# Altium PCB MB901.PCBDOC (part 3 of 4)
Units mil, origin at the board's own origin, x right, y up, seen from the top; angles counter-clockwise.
Board outline 4505 x 7005 mil, 4 copper layers (TopLayer, GND, VCC, BottomLayer); 333 components, 312 nets, 1570 pads, 794 vias.
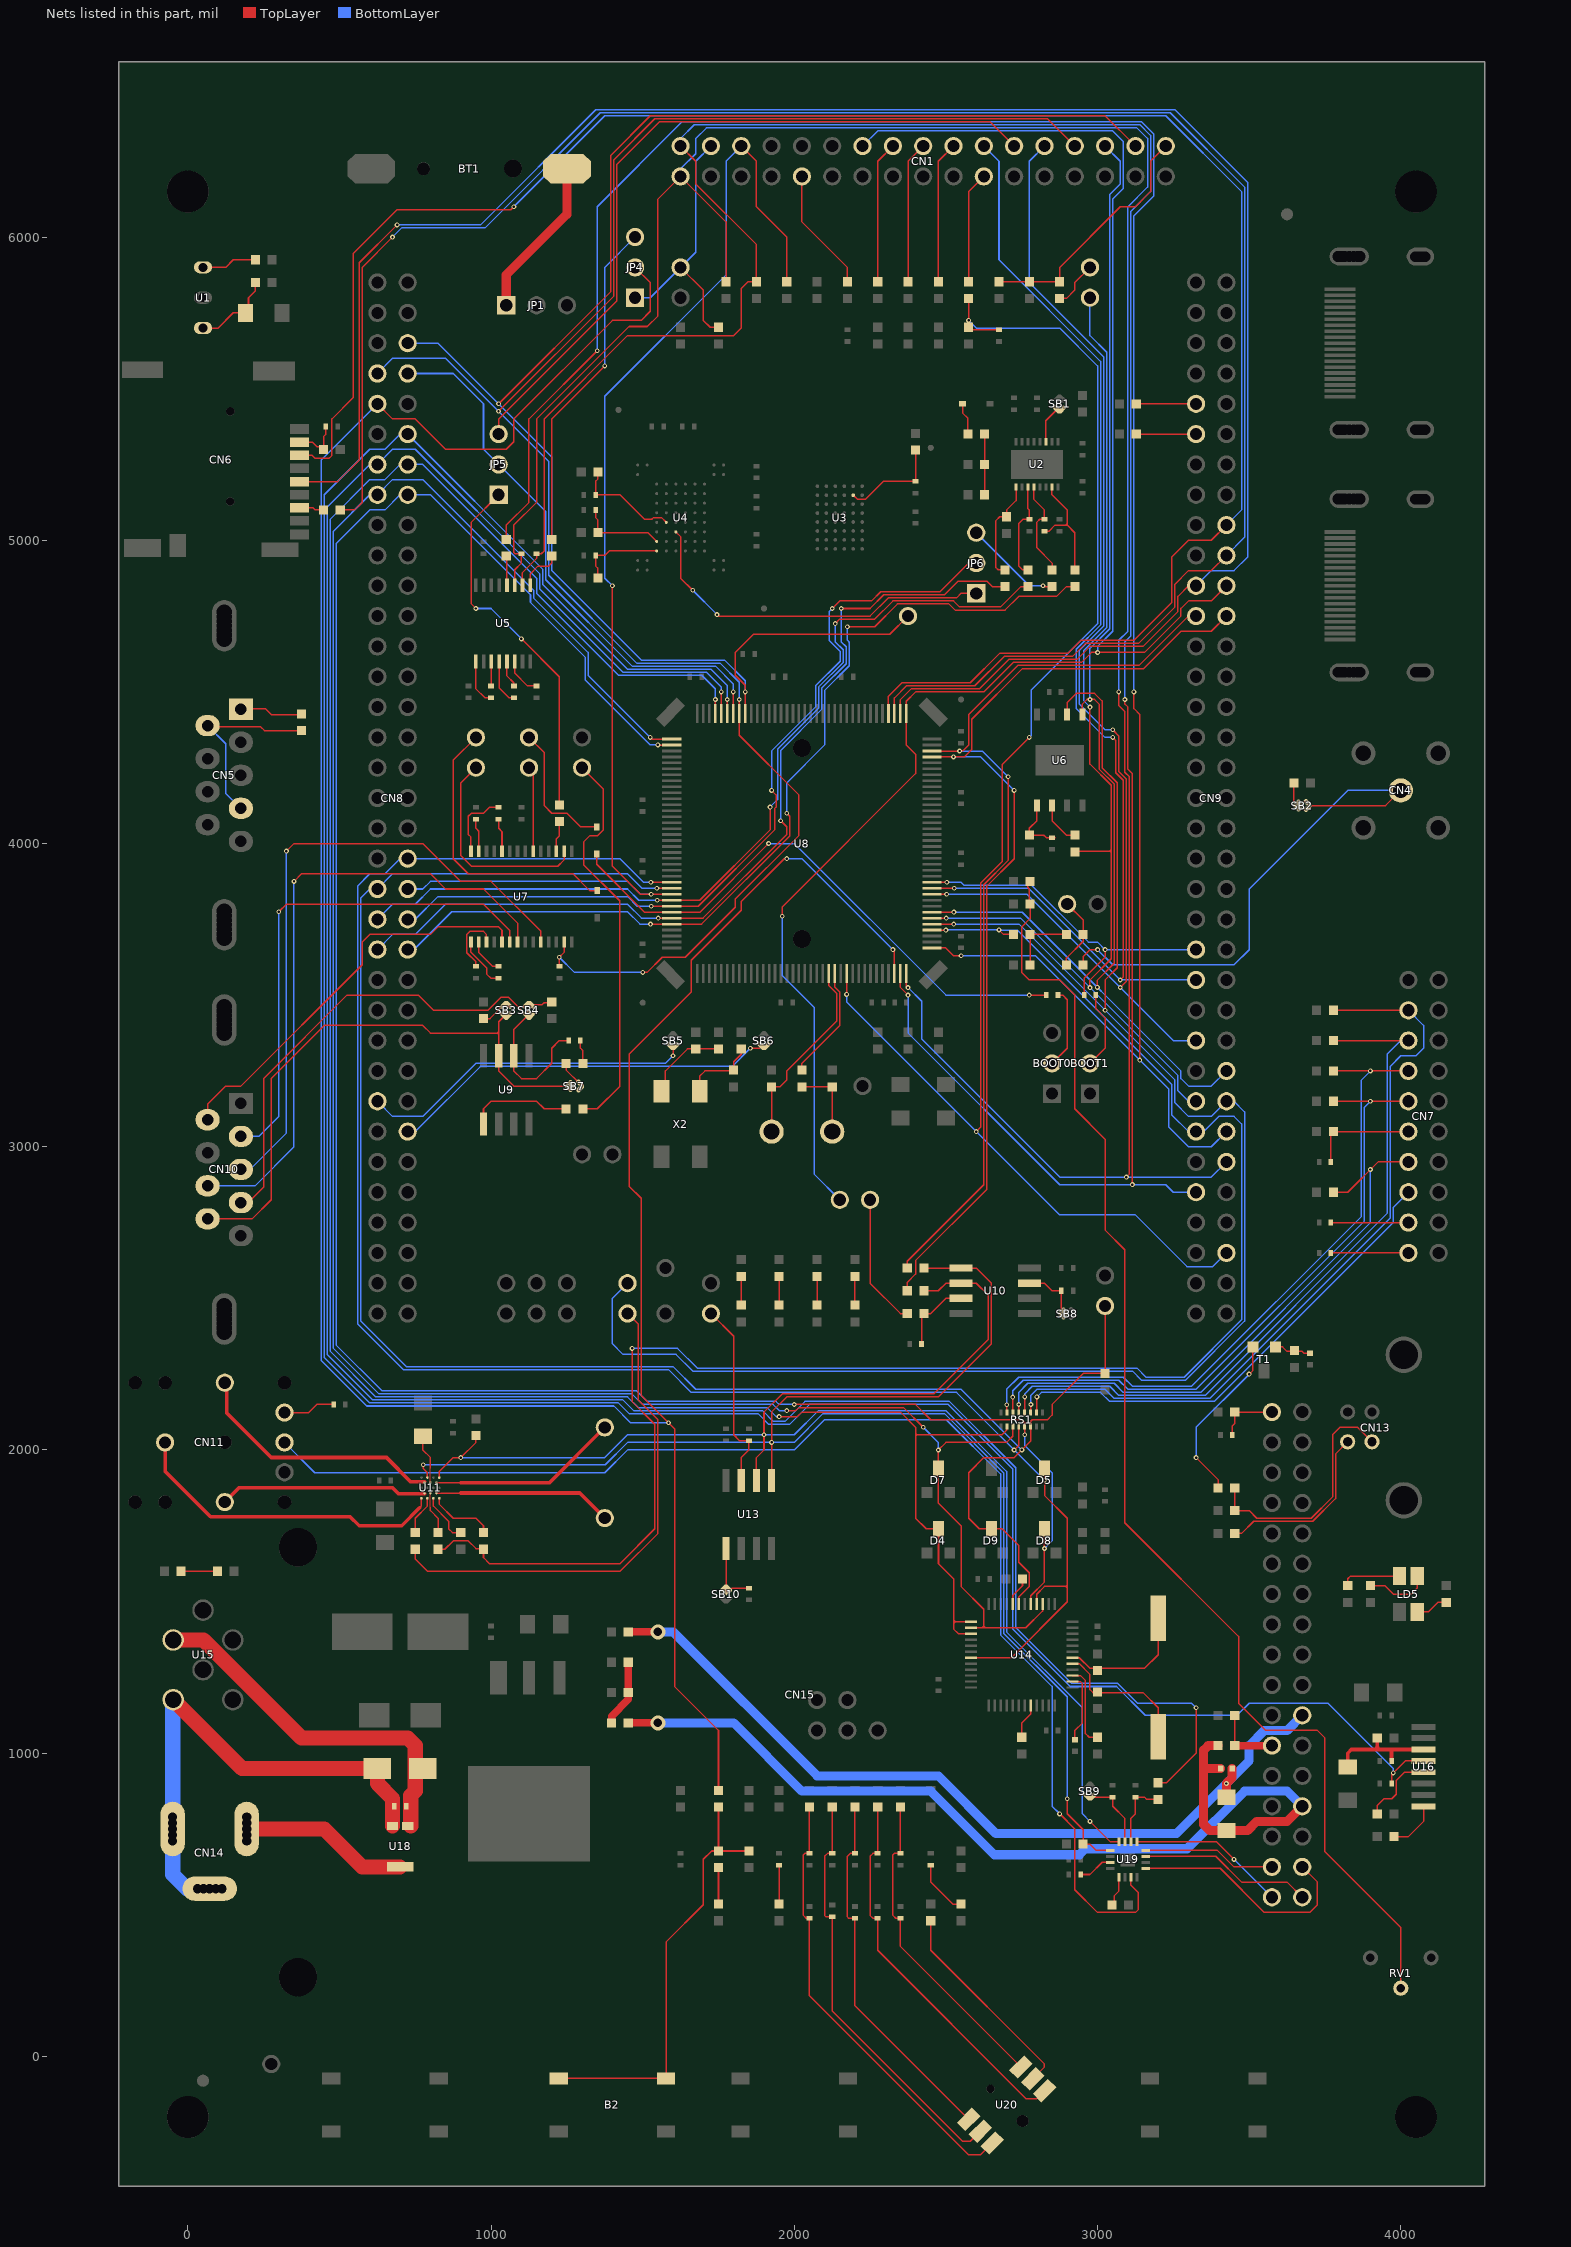
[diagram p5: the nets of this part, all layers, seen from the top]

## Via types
v1: diameter 16, hole 8, TopLayer to BottomLayer, tented both sides, 671 vias
v2: diameter 16, hole 8, TopLayer to BottomLayer, 117 vias
v3: diameter 50, hole 28, TopLayer to BottomLayer, 5 vias
v4: diameter 50, hole 28, TopLayer to BottomLayer, tented both sides, 1 vias

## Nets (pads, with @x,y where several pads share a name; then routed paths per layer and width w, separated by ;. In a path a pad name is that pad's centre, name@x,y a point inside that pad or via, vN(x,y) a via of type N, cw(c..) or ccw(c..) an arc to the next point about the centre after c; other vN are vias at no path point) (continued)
NetC25_1: C25.1 U5.1 | length 152.2
  TopLayer w5: U5.1@950,4600 950,4510 979.5,4480.5 C25.1@1000,4480.5
NetC25_2: C25.2 U5.3 | length 79.3
  TopLayer w5: C25.2@1001.18,4520.68 U5.3@1001.18,4600
NetC27_2: C27.2 U5.6 | length 127.6
  TopLayer w5: U5.6@1077.95,4600 1077.95,4562.05 1120.5,4519.5 C27.2@1150,4519.5
NetC33_1: C33.1 U7.24 | length 110.5
  TopLayer w5: C33.1@1025,4080.5 1025,4050 1036.02,4038.98 U7.24@1036.02,3974.61
NetC33_2: C33.2 U7.28 | length 231.2
  TopLayer w5: U7.28@933.66,3974.61 933.66,4021.34 925,4030 925,4090 935,4100 975,4100 994.5,4119.5 C33.2@1025,4119.5
NetC42_1: C42.1 U7.1 | length 172.7
  TopLayer w5: U7.1@933.66,3675.39 933.66,3641.34 985,3590 985,3570 999.5,3555.5 C42.1@1025,3555.5
NetC42_2: C42.2 U7.2 | length 119.6
  TopLayer w5: U7.2@959.25,3675.39 959.25,3640.75 1005.5,3594.5 C42.2@1025,3594.5
NetC45_2: C45.2 R48.2 R49.1 | length 220
  TopLayer w5: C45.2@2777.5,3600 R48.2@2777.5,3700 R49.1@2897.5,3700
NetC50_1: C50.1 R59.1 X2.1 | length 265
  TopLayer w5: X2.1@1575,3190 1575,3250 1647.5,3322.5 R59.1@1750,3322.5
NetC52_1: C52.1 U8.23 X1.2 | length 637
  TopLayer w5: X1.2@1925,3050 C52.1@1925,3197.5 1952.5,3197.5 1975,3220 1975,3250 2140,3415 2140,3505 2113.58,3531.42 U8.23@2113.58,3570.87
NetC53_1: C53.1 R64.2 X1.1 | length 247.5
  TopLayer w5: R64.2@2025,3197.5 C53.1@2125,3197.5 X1.1@2125,3050
NetC63_1: C63.1 U11.A5 | length 130
  TopLayer w5: C63.1@750,1727.5 750,1775 790.16,1815.16 U11.A5@790.16,1840.91
NetC64_1: C64.1 U11.B4 | length 138.2
  TopLayer w3: 800,1810.86 U11.B4@800,1855.32
  TopLayer w5: 800,1810.86 800,1800 825,1775 C64.1@825,1727.5
NetC65_1: C65.1 U11.A3 | length 187.3
  TopLayer w5: 809.84,1835.63 809.84,1815.16 ; U11.A3@809.84,1840.91 809.84,1815.16 ; C65.1@900,1727.5 872.5,1727.5 860,1740 860,1765 809.84,1815.16
NetC66_1: C66.1 U11.A1 | length 232.8
  TopLayer w5: 829.53,1835.63 829.53,1820.47 ; U11.A1@829.53,1840.91 829.53,1820.47 ; C66.1@975,1727.5 975,1750 950,1775 875,1775 829.53,1820.47
NetC85_1: C85.1 R124.2 | length 120
  TopLayer w5: R124.2@1750,502.5 C85.1@1750,622.5
NetC85_2: B2.2 B2.3 C85.2 R101.1 R116.1 | length 1429.4
  TopLayer w5: B2.2@1227.5,-72.5 B2.3@1577.17,-72.5 1577.17,377.17 1700,500 1700,650 1727.5,677.5 R116.1@1850,677.5 ; C85.2@1750,677.5 R101.1@1750,822.5
NetC86_1: C86.1 R125.2 | length 128
  TopLayer w5: R125.2@1950,502.5 C86.1@1950,630.5
NetC87_1: C87.1 R128.2 | length 185.5
  TopLayer w5: C87.1@2450,630.5 2450,575 2522.5,502.5 R128.2@2550,502.5
NetC93_2: C93.2 C94.2 CN15.22 L2.2 | length 2791.7
  TopLayer w25: L2.2@1452.5,1400 v3(1550,1400)
  TopLayer w30: C94.2@3425,855 v2(3425,900) 3444,919 C93.2@3444,950
  BottomLayer w30: v3(1550,1400) 1600,1400 2075,925 2475,925 2665,735 3260,735 3500,975 3500,1025 3550,1075 3625,1075 CN15.22@3675,1125
NetCN1_14: CN1.14 R7.1 | length 368.2
  TopLayer w5: R7.1@2575,5852.5 2575,6150 CN1.14@2625,6200
NetCN1_26: CN1.26 R3.1 | length 409.6
  TopLayer w5: CN1.26@2025,6200 2025,6050 2175,5900 R3.1@2175,5852.5
NetCN7_11: CN7.11 R67.1 R68.2 | length 339.5
  TopLayer w5: R68.2@3769.5,2950 R67.1@3769.5,3042 ; R67.1@3777.5,3050 CN7.11@4025,3050
NetCN7_17: CN7.17 R70.2 | length 255.5
  TopLayer w5: R70.2@3769.5,2750 CN7.17@4025,2750
NetCN7_19: CN7.19 R71.2 | length 255.5
  TopLayer w5: R71.2@3769.5,2650 CN7.19@4025,2650
NetCN10_4: C49.2 CN10.4 SB4.2 U9.6 | length 1979.9
  TopLayer w5: CN10.4@175,2816 199,2816 250,2867 250,3225 525,3500 760,3500 810,3450 990,3450 1033.59,3493.59 1056.41,3493.59 SB4.2@1118,3432 ; SB4.2@1125,3437 1075,3387 1075,3250 1100,3225 1150,3225 1200,3275 1200,3325 1225,3350 C49.2@1255.5,3350
NetCN10_9: CN10.9 SB3.2 SB7.2 U9.7 | length 1935.1
  TopLayer w5: CN10.9@65,2762 212,2762 275,2825 275,3225 450,3400 775,3400 800,3375 1025,3375 ; 1025,3370 1020,3375 1025,3380 ; SB3.2@1052,3437 SB3.2@1050,3437 1025,3412 1025,3250 1075,3200 SB7.2@1257,3200
NetCN11_5: CN11.5 U19.11 | length 4383.7
  TopLayer w5: v2(2875,800) 2925,750 2925,550 3000,475 3125,475 3135,485 3135,540 3109.84,565.16 U19.11@3109.84,591.26
  BottomLayer w5: CN11.5@318.7,2025 418.7,1925 1375,1925 1450,2000 2000,2000 2100,2100 2501,2100 2680,1921 2680,1390 2850,1220 2850,825 v2(2875,800)
NetCN13_2: CN13.2 R133.2 | length 583.7
  TopLayer w5: R133.2@3452.5,1725 3475,1725 3515,1765 3710,1765 3785,1840 3785,1987 CN13.2@3825,2027
NetCN13_3: CN13.3 R134.2 R135.2 | length 802.1
  TopLayer w5: R135.2@3452.5,1875 R134.2@3452.5,1800 3500,1800 3525,1775 3705,1775 3775,1845 3775,2050 3800,2075 3857,2075 CN13.3@3905,2027
NetCN14_1: CN14.1 U18.1 | length 557.7
  TopLayer w50: CN14.1@194.1,750 450,750 575,625 U18.1@700,625
NetCN14_3: C81.2 CN14.2 CN14.3 U15.2 U18.2 Z1.1 | length 1714.6
  TopLayer w50: U15.2@-48.43,1176.57 178.15,950 Z1.1@625.2,950 625.2,899.8 675,850 U18.2@675,760
  BottomLayer w50: U15.2@-50,1175 -50,600 -3.15,553.15 CN14.2@92.05,553.15
NetCN15_31: CN15.31 U19.16 | length 438.8
  TopLayer w5: U19.16@3158.74,679.53 3395.47,679.53 3450,625 CN15.31@3575,625
NetCN15_32: CN15.32 U19.13 | length 782.6
  TopLayer w5: U19.13@3158.74,620.47 3404.53,620.47 3550,475 3700,475 3725,500 3725,575 CN15.32@3675,625
NetCN15_33: CN15.33 U19.1 | length 521.6
  TopLayer w5: U19.1@3129.53,708.74 3391.26,708.74 v1(3450,650)
  BottomLayer w5: v1(3450,650) CN15.33@3575,525
NetCN15_34: CN15.34 U19.15 | length 572.1
  TopLayer w5: U19.15@3158.74,659.84 3390.16,659.84 3475,575 3625,575 CN15.34@3675,525
NetD2_2: D2.2 R52.1 U8.138 | length 1881.9
  TopLayer w5: D2.2@1348.28,3965 1348.28,3931.72 1506.38,3773.62 1688.62,3773.62 v2(1915,4000) ; v1(2775,3500) R52.1@2830.5,3500
  BottomLayer w5: v2(1915,4000) 2000,4000 2500,3500 v1(2775,3500)
NetD3_2: D3.2 JP7.1 | length 949.6
  TopLayer w5: JP7.1@950,4350 875,4275 875,3950 925,3900 1270,3900 1325,3845 D3.2@1350,3845
NetJP1_1: BT1.1 JP1.1 | length 532.8
  TopLayer w30: JP1.1@1050,5775 1050,5875 1250,6075 BT1.1@1250,6225
NetJP3_2: JP3.2 R8.2 | length 157.1
  TopLayer w5: R8.2@2875,5797.5 2897.5,5797.5 2925,5825 2925,5850 JP3.2@2975,5900
NetJP4_1: C13.2 CN1.31 JP2.1 JP4.1 | length 898.2
  TopLayer w5: JP2.1@1625,5900 1700,5825 1700,5725 1722.5,5702.5 C13.2@1750,5702.5
  BottomLayer w5: JP4.1@1475,5800 1525,5800 1675,5950 1675,6250 CN1.31@1725,6300
NetJP4_3: JP4.3 R33.2 | length 1111.4
  TopLayer w5: R33.2@1200,5002.5 1200,5400 v2(1375,5575)
  BottomLayer w5: v2(1375,5575) 1375,5900 JP4.3@1475,6000
NetJP5_1: JP5.1 R43.2 | length 1209.2
  TopLayer w5: v2(950,4775) 935,4790 935,5060 JP5.1@1025,5150 ; v2(1100,4675) 1225,4550 R43.2@1225,4127.5
  BottomLayer w5: v2(950,4775) 1000,4775 v2(1100,4675)
NetJP5_3: CN1.11 JP5.3 | length 2452.7
  TopLayer w5: JP5.3@1025,5350 1025,5400 1415,5790 1415,6240 1555,6380 2645,6380 CN1.11@2725,6300
NetJP6_1: JP6.1 U4.F3 | length 1217.1
  TopLayer w5: U4.F3@1609.25,5027.76 1625,5012.01 1625,4875 v1(1665,4835) ; v1(1745,4755) 1750,4750 2250,4750 2310,4810 2535,4810 2550,4825 JP6.1@2600,4825
  BottomLayer w5: v1(1665,4835) v1(1745,4755)
NetJP7_2: JP7.2 U7.16 | length 703.4
  TopLayer w5: JP7.2@950,4250 900,4200 900,3960 935,3925 1220,3925 1240.75,3945.75 U7.16@1240.75,3974.61
NetJP8_1: D2.1 JP8.1 | length 448
  TopLayer w5: JP8.1@1125,4350 1175,4300 1175,4125 1200,4100 1250,4100 1295,4055 D2.1@1348.28,4055
NetJP8_2: JP8.2 U7.20 | length 280.9
  TopLayer w5: JP8.2@1125,4250 1138.39,4236.61 U7.20@1138.39,3974.61
NetJP9_1: JP9.1 R66.2 | length 1323.1
  TopLayer w5: JP9.1@1300,4250 1370,4180 1370,4045 1350,4025 1325,4025 1305,4005 1305,3930 1424.08,3810.92 1424.08,3199.08 1350,3125 R66.2@1302.5,3125
NetJP15_1: C63.2 JP15.1 | length 1667.3
  TopLayer w5: C63.2@750,1672.5 750,1640 790,1600 1425,1600 1550,1725 1550,2100 1485,2165 1485,2415 JP15.1@1450,2450
NetL3_2: C93.1 C94.1 CN15.28 L3.2 R98.2 | length 3231.5
  TopLayer w25: L3.2@1452.5,1100 v3(1550,1100)
  TopLayer w30: 3350,950 C93.1@3406,950 ; R98.2@3397.5,1025 3365,1025 3350,1010 3350,765 3370,745 3495,745 3525,775 3625,775 CN15.28@3675,825
  BottomLayer w30: v3(1550,1100) 1800,1100 2025,875 2450,875 2660,665 2940,665 2960,685 3295,685 3485,875 3625,875 CN15.28@3675,825
NetLD1_1: LD1.1 R76.1 | length 95
  TopLayer w5: LD1.1@2200,2477.5 R76.1@2200,2572.5
NetLD2_1: LD2.1 R75.1 | length 95
  TopLayer w5: LD2.1@2075,2477.5 R75.1@2075,2572.5
NetLD3_1: LD3.1 R74.1 | length 102.5
  TopLayer w5: LD3.1@1950,2470 R74.1@1950,2572.5
NetLD4_1: LD4.1 R73.1 | length 102.5
  TopLayer w5: LD4.1@1825,2470 R73.1@1825,2572.5
NetLD5_3: LD5.3 R90.2 | length 213.5
  TopLayer w5: R90.2@3900,1552.5 3947.5,1552.5 3975,1525 4035,1525 4054.53,1544.53 LD5.3@4054.53,1584.06
NetLD5_4: LD5.4 R131.1 | length 108.5
  TopLayer w5: LD5.4@4054.53,1465.94 4090.94,1465.94 4122.5,1497.5 R131.1@4150,1497.5
NetR4_2: CN1.19 R4.2 | length 468.2
  TopLayer w5: R4.2@2275,5852.5 2275,6250 CN1.19@2325,6300
NetR5_2: CN1.17 R5.2 | length 468.2
  TopLayer w5: R5.2@2375,5852.5 2375,6250 CN1.17@2425,6300
NetR6_2: CN1.15 R6.2 | length 468.2
  TopLayer w5: R6.2@2475,5852.5 2475,6250 CN1.15@2525,6300
NetR10_1: C11.2 CN1.1 R8.1 R10.1 | length 821.8
  TopLayer w5: C11.2@2675,5852.5 R8.1@2875,5852.5 2875,5900 3075,6100 3125,6100 3175,6150 3175,6250 CN1.1@3225,6300
NetR11_2: CN9.9 R11.2 | length 197.5
  TopLayer w5: R11.2@3127.5,5450 CN9.9@3325,5450
NetR12_1: R12.1 R19.1 R26.2 | length 200
  TopLayer w5: R26.2@2627.5,5150 R12.1@2627.5,5350
NetR12_2: D1.1 R12.2 | length 107.2
  TopLayer w5: D1.1@2555,5450 2555,5420 2572.5,5402.5 R12.2@2572.5,5350
NetR16_2: CN6.2 R15.1 R16.2 | length 156.6
  TopLayer w5: CN6.2@368.35,5323.62 411.38,5323.62 427,5308 447,5308 447.5,5307.5 447.5,5342 455.5,5350 R15.1@455.5,5375
NetR18_1: R18.1 R23.1 U3.B5 | length 326.6
  TopLayer w5: U3.B5@2194.29,5148.82 2208.11,5135 2235,5135 2294.5,5194.5 R23.1@2400,5194.5 R18.1@2400,5285
NetR20_1: CN9.11 R20.1 | length 197.5
  TopLayer w5: R20.1@3127.5,5350 CN9.11@3325,5350
NetR22_1: R21.1 R22.1 U4.E2 | length 353.9
  TopLayer w5: R22.1@1352.5,5225 1352.5,5202.5 1344.5,5194.5 R21.1@1344.5,5150 1425,5150 1505.75,5069.25 1530,5069.25 1535.75,5075 1562.01,5075 U4.E2@1577.76,5059.25
NetR24_1: CN6.7 R24.1 | length 82.1
  TopLayer w5: CN6.7@368.35,5107.09 412.91,5107.09 420,5100 R24.1@447.5,5100
NetR32_2: R32.2 R36.1 U4.H1 | length 286.2
  TopLayer w5: R36.1@1352.5,4875 1352.5,4907.5 1344.5,4915.5 R32.2@1344.5,4950 1375,4950 1389.76,4964.76 U4.H1@1546.26,4964.76
NetR35_1: R30.1 R35.1 U2.7 | length 399.2
  TopLayer w5: R30.1@2825,5030.5 2840.5,5030.5 2860,5050 2900,5050 ; U2.7@2849.21,5175.2 2849.21,5150.79 2900,5100 2900,5050 ; 2900,5055 2895,5050 2900,5050 ; R35.1@2925,4902.5 2925,5025 2900,5050
NetR37_1: R29.2 R37.1 U2.1 | length 338.9
  TopLayer w5: R37.1@2695,4902.5 2672.5,4902.5 2665,4910 2665,5065 2677.5,5077.5 R29.2@2700,5077.5 2700,5100 2731.1,5131.1 U2.1@2731.1,5175.2
NetR38_1: R34.2 R38.1 U2.3 | length 323.8
  TopLayer w5: R38.1@2770,4902.5 2752.5,4902.5 2740,4915 2740,5055 2754.5,5069.5 R34.2@2775,5069.5 2775,5100 2770.47,5104.53 U2.3@2770.47,5175.2
NetR39_1: R30.2 R39.1 U2.4 | length 327.3
  TopLayer w5: U2.4@2790.16,5175.2 2790.16,5134.84 2825,5100 R30.2@2825,5069.5 2809.5,5069.5 2800,5060 2800,4975 2850,4925 R39.1@2850,4902.5
NetR39_2: JP6.3 R39.2 | length 323.5
  TopLayer w5: v1(2820,4850) 2822.5,4847.5 R39.2@2850,4847.5
  BottomLayer w5: JP6.3@2600,5025 2775,4850 v1(2820,4850)
NetR41_1: CN5.4 CN5.6 R41.1 | length 612.7
  TopLayer w5: CN5.6@80,4385 240,4385 252.5,4372.5 R41.1@375,4372.5
  BottomLayer w5: CN5.6@65,4389 125,4329 125,4165 CN5.4@170,4120
NetR41_2: CN5.1 R41.2 | length 195.8
  TopLayer w5: CN5.1@185,4445 255,4445 275,4425 R41.2@372.5,4425
NetR42_1: R42.1 SB2.2 | length 81
  TopLayer w5: R42.1@3647.5,4200 3647.5,4139.5 SB2.2@3662,4125
NetR43_1: R43.1 U7.17 | length 102
  TopLayer w5: U7.17@1215.16,3974.61 1215.16,4015.16 1225,4025 R43.1@1225,4072.5
NetR44_1: R44.1 R45.1 U6.1 | length 196.2
  TopLayer w5: U6.1@2800,4125 2800,4075 2775,4050 R44.1@2775,4027.5 2822.5,4027.5 2830.5,4019.5 2860,4019.5
NetR46_2: R46.2 U6.2 | length 154.7
  TopLayer w5: U6.2@2850,4125 2850,4075 2897.5,4027.5 R46.2@2935,4027.5
NetR47_2: C40.2 R47.2 RV1.2 | length 4340.6
  TopLayer w5: C40.2@2769.5,3875 2769.5,3855.5 2775,3850 2775,3802.5 R47.2@2777.5,3800 2777.5,3752.5 2750,3725 2750,3575 2775,3550 2875,3550 2925,3500 2925,3125 3025,3025 3025,2725 3090,2660 3090,1760 3465,1385 3465,1165 3555,1075 3725,1075 3750,1050 3750,675 4000,425 RV1.2@4000,225
NetR49_2: R49.2 R51.1 TP1.1 | length 244.5
  TopLayer w5: R51.1@2897.5,3600 2897.5,3622.5 2952.5,3677.5 2952.5,3747.5 TP1.1@2900,3800
NetR51_2: CN4.5 R51.2 SB2.1 | length 1786.1
  TopLayer w5: R51.2@2952.5,3600 2952.5,3627.5 2975,3650 v1(3000,3650) ; SB2.1@3695,4125 3950,4125 CN4.5@4000,4175
  BottomLayer w5: v1(3000,3650) 3050,3600 3450,3600 3500,3650 3500,3850 3825,4175 CN4.5@4000,4175
NetR52_2: BOOT0.2 R52.2 | length 267.4
  TopLayer w5: BOOT0.2@2850,3275 2900,3325 2900,3485 2885,3500 R52.2@2869.5,3500
NetR53_2: BOOT1.2 R53.2 | length 258.3
  TopLayer w5: BOOT1.2@2975,3275 3025,3325 3025,3425 2994.5,3455.5 R53.2@2994.5,3500
NetR55_1: R55.1 SB3.1 | length 85.8
  TopLayer w5: R55.1@975,3422.5 996.5,3422.5 SB3.1@1042,3468
NetR56_1: R56.1 SB4.1 | length 67.4
  TopLayer w5: SB4.1@1133,3468 1168,3468 1175,3475 R56.1@1197.5,3475
NetR58_1: C49.1 R58.1 | length 78.3
  TopLayer w5: C49.1@1294.5,3350 1294.5,3325.5 1302.5,3317.5 R58.1@1302.5,3275
NetR58_2: R58.2 SB7.1 | length 85.8
  TopLayer w5: R58.2@1247.5,3275 1247.5,3253.5 SB7.1@1293,3208
NetR64_1: R64.1 U8.24 | length 377.1
  TopLayer w5: R64.1@2025,3252.5 2025,3275 2150,3400 2150,3510 2133.27,3526.73 U8.24@2133.27,3570.87
NetR66_1: R66.1 U9.1 | length 343.2
  TopLayer w5: U9.1@975,3075 975,3125 1000,3150 1150,3150 1175,3125 R66.1@1247.5,3125
NetR72_1: R72.1 R112.2 U10.1 U11.E5 U13.5 U19.5 | length 5029.7
  TopLayer w5: v1(776.41,1951.41) 776.41,1938.75 790.16,1925 U11.E5@790.16,1909.09 ; U13.5@1925,1900 1925,2125 1975,2175 2475,2175 2650,2350 2650,2550 2600,2600 R72.1@2427.5,2600 ; v2(2900,850) 2900,800 2952.5,747.5 R112.2@2952.5,700 2975,700 2995.47,679.53 U19.5@3041.26,679.53
  BottomLayer w5: v1(776.41,1951.41) 1376.41,1951.41 1450,2025 2000,2025 2095,2120 2495.15,2120 2690,1925.15 2690,1395.86 2900,1185.86 v2(2900,850)
  other v2: 1925,2025
NetR77_1: R77.1 R83.2 U10.2 U11.E1 U13.6 U19.4 | length 5008.6
  TopLayer w5: U11.E1@829.53,1909.09 829.53,1929.53 875,1975 v1(900,1975) 950,2025 R83.2@950,2055.5 ; U13.6@1875,1900 1875,1975 1900,2000 1900,2125 1960,2185 2460,2185 2640,2365 2640,2510 2600,2550 2500,2550 2475,2525 R77.1@2427.5,2525 ; v2(2975,775) 3041.26,708.74 U19.4@3070.47,708.74
  BottomLayer w5: v1(900,1975) 1375,1975 1450,2050 2000,2050 2080,2130 2499.29,2130 2700,1929.29 2700,1400 2950,1150 2950,800 v2(2975,775)
  other v2: 1900,2050
NetR78_1: JP11.2 R78.1 | length 438.9
  TopLayer w5: JP11.2@2250,2825 2250,2550 2350,2450 R78.1@2372.5,2450
NetR82_2: CN11.6 R82.2 | length 172.8
  TopLayer w5: CN11.6@318.7,2123.43 398.43,2123.43 425,2150 R82.2@480.5,2150
NetR85_1: CN15.1 R84.1 R85.1 | length 200.8
  TopLayer w5: R84.1@3444.5,2050 3444.5,2079.5 3452.5,2087.5 R85.1@3452.5,2125 CN15.1@3575,2125
NetR89_1: LD5.2 R89.1 | length 196.7
  TopLayer w5: R89.1@3825,1552.5 3825,1575 3834.06,1584.06 LD5.2@3995.47,1584.06
NetR92_1: LD6.1 R92.1 | length 120
  TopLayer w5: LD6.1@-22.5,1600 R92.1@97.5,1600
NetR95_2: CN15.23 R95.2 R98.1 | length 222.5
  TopLayer w5: R98.1@3452.5,1025 R95.2@3452.5,1125
  TopLayer w25: R98.1@3452.5,1025 CN15.23@3575,1025
NetR96_2: C80.1 C82.1 R96.2 U16.6 | length 443.2
  TopLayer w5: 3910,1012.5 3922.5,1025 3922.5,1024.51 3935,1012.01 ; 3957.49,1012.01 3969.5,1000 3969.5,1001.51 3980,1012.01
  TopLayer w12: C82.1@3825,955 3825,1000 3837.01,1012.01 U16.6@4075,1012.01 ; 3922.5,1012.5 R96.2@3922.5,1050 ; C80.1@3969.5,975 3969.5,1011.51
NetR97_2: R97.2 U14.3 | length 269.5
  TopLayer w5: U14.3@2917.32,1256.1 2943.9,1256.1 2960,1240 2960,1065 2972.5,1052.5 R97.2@3000,1052.5
NetR104_1: C88.2 R104.1 R117.1 U20.3 | length 1490.9
  TopLayer w5: R104.1@2050,822.5 R117.1@2050,669.5 2034.5,669.5 2030,665 2030,465 2039.5,455.5 C88.2@2050,455.5 2050,200 2575,-325 2612.95,-325 U20.3@2652.67,-285.27
NetR105_1: C89.2 R105.1 R118.2 U20.2 | length 1395.1
  TopLayer w5: R105.1@2125,822.5 R118.2@2125,669.5 2109.5,669.5 2100,660 2100,465 2104.5,460.5 C89.2@2125,460.5 2125,150 2555,-280 2580,-280 U20.2@2613.7,-246.3
NetR106_1: C90.2 R106.1 R119.1 U20.1 | length 1226.8
  TopLayer w5: R106.1@2200,822.5 R119.1@2200,669.5 2184.5,669.5 2175,660 2175,460 2179.5,455.5 C90.2@2200,455.5 2200,167.4 U20.1@2574.73,-207.33
NetR107_1: C91.2 R107.1 R120.1 U20.4 | length 1275.9
  TopLayer w5: R107.1@2275,822.5 R120.1@2275,669.5 2259.5,669.5 2250,660 2250,465 2259.5,455.5 C91.2@2275,455.5 2275,350 2765,-140 2797.95,-140 U20.4@2825.27,-112.67
NetR108_1: C92.2 R108.1 R121.1 U20.6 | length 1063.6
  TopLayer w5: R108.1@2350,822.5 R121.1@2350,669.5 2329.5,669.5 2325,665 2325,465 2334.5,455.5 C92.2@2350,455.5 2350,362.6 U20.6@2747.33,-34.73
NetR110_1: R110.1 U16.4 | length 251.8
  TopLayer w5: R110.1@3922.5,800 3922.5,827.5 3945,850 3970,850 3985,865 3985,910 4012.2,937.2 U16.4@4075,937.2
NetR115_2: R115.2 U16.1 | length 168.2
  TopLayer w5: R115.2@3977.5,725 4025,725 4075,775 U16.1@4075,825
NetR126_1: R126.1 U19.9 | length 97.5
  TopLayer w5: R126.1@3055.5,500 3055.5,530.5 3070.47,545.47 U19.9@3070.47,591.26
NetR127_2: R127.2 U20.5 | length 692.6
  TopLayer w5: R127.2@2450,447.5 2450,350 2825,-25 2825,-35 U20.5@2786.3,-73.7
NetR129_2: R129.2 U14.2 | length 231.7
  TopLayer w5: U14.2@2917.32,1236.42 2943.58,1236.42 2950,1230 2950,1100 2925,1075 R129.2@2925,1044
NetR130_2: R130.2 R132.1 T1.2 | length 121.2
  TopLayer w5: T1.2@3587.5,2340 3610,2340 3625,2325 3675,2325 3681,2319 R130.2@3700,2319
NetR135_1: R135.1 T1.1 | length 572.7
  TopLayer w5: v2(3325,1975) 3397.5,1902.5 R135.1@3397.5,1875 ; v2(3500,2250) 3512.5,2262.5 T1.1@3512.5,2340
  BottomLayer w5: v2(3325,1975) 3325,2075 v2(3500,2250)
NetR136_2: L3.1 R136.2 R137.2 | length 222.8
  TopLayer w25: L3.1@1397.5,1100 1397.5,1122.5 1452.5,1177.5 R136.2@1452.5,1300
NetRS1_4: CN7.7 R63.1 RS1.4 | length 2247.6
  TopLayer w5: RS1.4@2700.79,2123 v1(2700.79,2149.21) ; R63.1@3777.5,3250 CN7.7@4025,3250
  BottomLayer w5: v1(2700.79,2149.21) 2700.79,2200.79 2740,2240 3085,2240 3115,2210 3310,2210 3870,2770 3870,3220 v1(3900,3250)
NetRS1_6: CN7.9 R65.2 RS1.6 | length 2139.4
  TopLayer w5: RS1.6@2720.47,2123 v1(2720.47,2174.53) ; R65.2@3777.5,3150 CN7.9@4025,3150
  BottomLayer w5: v1(2720.47,2174.53) 2720.47,2195.47 2755,2230 3070,2230 3100,2200 3325,2200 3880,2755 3880,3130 v1(3900,3150)
NetRS1_8: CN7.13 R69.1 RS1.8 | length 1947.8
  TopLayer w5: v1(2740,2150) 2740.16,2149.84 RS1.8@2740.16,2123 ; R69.1@3777.5,2850 3825,2850 3925,2950 CN7.13@4025,2950
  BottomLayer w5: v1(2740,2150) 2740,2190 2770,2220 3055,2220 3085,2190 3340,2190 3900,2750 v1(3900,2925)
NetRS1_10: CN7.5 R57.1 RS1.10 | length 2389.3
  TopLayer w5: RS1.10@2759.84,2123 v1@2759.84,2174.84 ; R57.1@3777.5,3350 CN7.5@4025,3350
  BottomLayer w5: v1(2760,2175) 2760,2185 2785,2210 3040,2210 3070,2180 3355,2180 3955,2780 3955,3305 4000,3350 CN7.5@4025,3350
NetRS1_12: CN7.3 R54.1 RS1.12 | length 2537.4
  TopLayer w5: RS1.12@2779.53,2123 2779.53,2149.53 v1(2780,2150) ; R54.1@3777.5,3450 CN7.3@4025,3450
  BottomLayer w5: v1(2780,2150) 2780,2180 2800,2200 3025,2200 3055,2170 3370,2170 3965,2765 3965,3265 4000,3300 4050,3300 4075,3325 4075,3400 CN7.3@4025,3450
NetRS1_14: CN7.15 RS1.14 | length 1611.1
  TopLayer w5: RS1.14@2799.21,2123 2799.21,2174.21 v1(2800,2175)
  BottomLayer w5: v1(2800,2175) 2815,2190 3010,2190 3040,2160 3385,2160 3975,2750 3975,2800 CN7.15@4025,2850
NetSB5_1: CN8.55 SB5.1 | length 1101.5
  TopLayer w5: v1(1600,3300) SB5.1@1600,3330
  BottomLayer w5: CN8.55@630,3145 675,3100 775,3100 950,3275 1575,3275 v1(1600,3300)
NetSB6_1: CN8.58 SB6.1 | length 1283.8
  TopLayer w5: v1(1855,3325) 1885,3325 SB6.1@1892,3332
  BottomLayer w5: CN8.58@725,3050 750,3050 965,3265 1795,3265 v1(1855,3325)
NetSB8_2: R79.1 SB8.2 U10.7 | length 182.4
  TopLayer w5: U10.7@2775,2550 2825,2550 2850,2525 R79.1@2880.5,2525 SB8.2@2880.5,2458.5
NetSB10_2: R94.2 SB10.2 U13.1 | length 206.5
  TopLayer w5: SB10.2@1775,1544.5 U13.1@1775,1675 ; SB10.2@1780,1530 1794.5,1544.5 R94.2@1850,1544.5
NetU1_1: R1.2 U1.1 | length 182.9
  TopLayer w5: U1.1@50,5900 125,5900 150,5925 R1.2@222.5,5925
NetU1_3: C2.1 R2.1 U1.3 | length 290
  TopLayer w5: U1.3@50,5700 100,5700 150,5750 C2.1@210,5750 ; C2.1@200,5750 200,5800 222.5,5822.5 R2.1@222.5,5850
NetU2_11: SB1.1 U2.11 | length 122.7
  TopLayer w5: U2.11@2829.53,5324.8 2829.53,5394.53 SB1.1@2867,5432
NetU4_G1: R25.2 R28.2 U4.G1 | length 284
  TopLayer w5: R25.2@1344.5,5100 1344.5,5075 1352.5,5067 R28.2@1352.5,5025 1517.52,5025 U4.G1@1546.26,4996.26
NetU5_4: C26.1 U5.4 | length 148.6
  TopLayer w5: U5.4@1026.77,4600 1026.77,4513.23 1059.5,4480.5 C26.1@1075,4480.5
NetU5_5: C26.2 U5.5 | length 89.9
  TopLayer w5: U5.5@1052.36,4600 1052.36,4552.64 1075,4530 C26.2@1075,4519.5
NetU5_9: R33.1 U5.9 | length 145.4
  TopLayer w5: U5.9@1129.13,4851.97 1129.13,4889.13 1155,4915 1190,4915 1200,4925 R33.1@1200,4947.5
NetU5_12: R138.1 U5.12 | length 93.2
  TopLayer w5: U5.12@1052.36,4851.97 R138.1@1052.36,4945.14
NetU7_3: C41.1 U7.3 | length 215.8
  TopLayer w5: C41.1@950,3594.5 950,3610 920,3640 920,3700 930,3710 975,3710 984.84,3700.16 U7.3@984.84,3675.39
NetU7_5: CN10.6 U7.5 | length 1351.4
  TopLayer w5: CN10.6@65,3089 65,3140 125,3200 175,3200 575,3600 575,3675 600,3700 800,3700 825,3725 1025,3725 1036.02,3713.98 U7.5@1036.02,3675.39
NetU7_6: CN10.2 U7.6 | length 1673.2
  TopLayer w5: v2(300,3775) 325,3800 975,3800 1061.61,3713.39 U7.6@1061.61,3675.39
  BottomLayer w5: CN10.2@175,3034 234,3034 300,3100 v2(300,3775)
NetU7_7: CN10.8 U7.7 | length 2090.6
  TopLayer w5: v2(350,3875) 375,3900 800,3900 850,3850 975,3850 1087.2,3737.8 U7.7@1087.2,3675.39
  BottomLayer w5: CN10.8@65,2871 221,2871 350,3000 v2(350,3875)
NetU7_10: CN10.3 U7.10 | length 2134.4
  TopLayer w5: v2(325,3975) 350,4000 775,4000 900,3875 1000,3875 1163.98,3711.02 U7.10@1163.98,3675.39
  BottomLayer w5: CN10.3@175,2925 205,2925 325,3045 v2(325,3975)
NetU7_27: C37.1 U7.27 | length 109.7
  TopLayer w5: C37.1@950,4080.5 950,4050 959.25,4040.75 U7.27@959.25,3974.61
NetU10_3: R78.2 R80.1 U10.3 | length 235.2
  TopLayer w5: R80.1@2419.5,2350 R78.2@2419.5,2442 ; R78.2@2427.5,2450 2450,2450 2500,2500 U10.3@2550,2500
NetU11_A7: CN11.1 U11.A7 | length 1067.6
  TopLayer w5: 764.21,1809.21 770.47,1815.47 U11.A7@770.47,1840.91
  TopLayer w12: CN11.1@-75,2025 -75,1930 75,1780 535,1780 565,1750 705,1750 764.21,1809.21
NetU11_B2: U11.B2 U12.1 | length 589.5
  TopLayer w5: U11.B2@819.68,1857.95 900,1857.95
  TopLayer w12: 900,1857.95 1292.44,1857.95 U12.1@1375,1775.39
NetU11_B6: CN11.2 U11.B6 | length 686
  TopLayer w12: CN11.2@121.85,1828.15 168.7,1875 675,1875 694.68,1855.32 U11.B6@780.32,1855.32
NetU11_D2: U11.D2 U12.2 | length 630.9
  TopLayer w5: U11.D2@819.68,1892.05 900,1892.05
  TopLayer w12: 900,1892.05 1192.44,1892.05 U12.2@1375,2074.61
NetU11_D4: C58.1 U11.D4 | length 160.7
  TopLayer w3: U11.D4@800,1894.68 800,1939.14
  TopLayer w5: C58.1@775,2045 775,2000 800,1975 800,1939.14
NetU11_D6: CN11.3 U11.D6 | length 848.9
  TopLayer w12: CN11.3@130,2220 128.15,2221.85 128.15,2121.85 275,1975 655,1975 735.32,1894.68 U11.D6@780.32,1894.68
NetU13_7: JP14.1 R86.2 U13.7 | length 630
  TopLayer w5: JP14.1@1725,2450 1800,2375 1800,2050 1819.5,2030.5 R86.2@1850,2030.5 1850,2000 1825,1975 U13.7@1825,1900
NetU14_20: R88.1 U14.20 | length 95.9
  TopLayer w5: U14.20@2720.47,1492.32 2720.47,1520 2752.5,1552.03 R88.1@2752.5,1575
NetU14_44: R81.2 U14.44 | length 117.4
  TopLayer w5: R81.2@2750,1052.5 2750,1100 2779.53,1129.53 U14.44@2779.53,1157.68
NetU18_3: C81.1 U15.1 U18.3 Z1.2 | length 1253.1
  TopLayer w5: C81.1@725,825 725,850 735,860
  TopLayer w50: U15.1@-48.43,1373.43 51.57,1373.43 375,1050 725,1050 750,1025 750,875 735,860 U18.3@735,760
NetU19_2: R99.2 R114.1 U19.2 | length 231.4
  TopLayer w5: U19.2@3109.84,708.74 3109.84,784.84 3125,800 R114.1@3125,855.5 3154.5,855.5 3162.5,847.5 R99.2@3200,847.5
NetU19_3: R113.1 SB9.1 U19.3 | length 228.9
  TopLayer w5: SB9.1@2984.5,855.5 R113.1@3050,855.5 3050,825 3090.16,784.84 U19.3@3090.16,708.74
NetU19_7: R123.1 U19.7 | length 113.4
  TopLayer w5: R123.1@2944.5,600 2975,600 3015.16,640.16 U19.7@3041.26,640.16
NetX2_4: C51.1 R60.1 X2.4 | length 246.6
  TopLayer w5: X2.4@1687.99,3183.27 1687.99,3232.99 1705,3250 C51.1@1797.5,3250 ; C51.1@1800,3252.5 1800,3280 1825,3305 R60.1@1825,3322.5
OSC_IN: C79.2 U14.5 X3.2 | length 467.2
  TopLayer w5: U14.5@2917.32,1295.47 2939.53,1295.47 2975,1260 2975,1210 2985,1200 3150,1200 3200,1150 X3.2@3200,1055
OSC_OUT: C75.2 U14.6 X3.1 | length 435.9
  TopLayer w5: U14.6@2917.32,1315.16 2940,1315.16 2975.16,1280 3155,1280 3200,1325 X3.1@3200,1445
PA0: CN8.9 JP4.2 R101.2 U8.34 | length 9792.3
  TopLayer w5: CN8.9@625,5450 675,5400 750,5400 850,5300 1050,5300 1075,5325 1075,5400 1400,5725 1495,5725 1525,5755 1525,5850 JP4.2@1475,5900 ; R101.2@1750,877.5 1750,1075 1605,1220 1605,2070 1495,2180 1495,2830 1455,2870 1455,3305 1660,3510 1660,3615 1825,3780 1825,3808.43 1966.57,3950 v1(1975,3950) ; v1(2325,3650) 2330.12,3644.88 U8.34@2330.12,3570.87
  BottomLayer w5: CN8.9@625,5450 440,5265 440,2295 590,2145 1405,2145 1460,2090 v2(1585,2090) ; v1(1975,3950) 2025,3950 v1(2325,3650)
PA1: C4.2 CN1.33 CN9.61 R27.2 U5.10 U8.35 | length 8588.8
  TopLayer w5: U5.10@1103.54,4851.97 1103.54,4893.54 1150,4940 R27.2@1150,4955.5 1165.5,4955.5 1175,4965 1175,5400 1450,5675 1800,5675 1825,5700 1825,5830 1847.5,5852.5 C4.2@1875,5852.5 1875,5975 1675,6175 1675,6250 CN1.33@1625,6300 ; U8.35@2349.8,3570.87 2349.8,3525.2 v1(2375,3500) ; v1(3090,4475) 3090,4460 3100,4450 3100,4245 3115,4230 v2(3115,2875)
  BottomLayer w5: CN1.33@1625,6300 1625,6325 1670,6370 3140,6370 3175,6335 3175,6150 3110,6085 3110,4685 3090,4665 v1(3090,4475) ; v1(2375,3500) 2375,3375 2875,2875 3225,2875 3250,2850 CN9.61@3325,2850
PA2: C5.2 CN1.34 CN9.60 R31.2 U5.11 U8.36 | length 8650.8
  TopLayer w5: U5.11@1077.95,4851.97 1077.95,4902.95 1100,4925 R31.2@1100,4955.5 1079.5,4955.5 1075,4960 1075,5050 1150,5125 1150,5400 1455,5705 1515,5705 1550,5740 1550,6125 CN1.34@1625,6200 1775,6050 C5.2@1775,5852.5 ; U8.36@2369.49,3570.87 2369.49,3530.51 v1(2375,3525) ; v1(3070,4500) 3070,4455 3090,4435 3090,4235 3105,4220 3105,2910 v2(3095,2900)
  BottomLayer w5: CN1.34@1625,6200 1625,6225 1675,6275 1675,6325 1710,6360 3130,6360 3165,6325 3165,6165 3100,6100 3100,4700 3070,4670 v1(3070,4500) ; v1(2375,3525) 2420,3480 2420,3355 2875,2900 3375,2900 CN9.60@3425,2950
PA3: CN9.58 R138.2 U8.37 | length 7614.6
  TopLayer w5: R138.2@1050,5002.5 1050,5050 1125,5125 1125,5400 v2(1350,5625) ; U8.37@2454.13,3655.51 2499.49,3655.51 2525,3630 v1(2550,3630) ; v2(3120,4500) 3120,4445 3139.1,4425.9 v2(3139.1,3285.9)
  BottomLayer w5: v2(1350,5625) 1350,6100 1630,6380 3145,6380 3185,6340 3185,6135 3120,6070 v2(3120,4500) ; v1(2550,3630) 2795,3630 3235,3190 3235,3065 3300,3000 3375,3000 CN9.58@3425,3050
PA4: C64.2 C66.2 CN9.57 R48.1 U8.40 | length 5660.1
  TopLayer w5: C64.2@825,1672.5 847.5,1672.5 875,1700 925,1700 950,1675 C66.2@975,1675 ; C66.2@975,1672.5 975,1645 995,1625 1425,1625 1540,1740 1540,2085 1465,2160 v2(1465,2335) ; U8.40@2454.13,3714.57 v1(2500,3714.57) ; v1(2675,3715) 2690,3700 R48.1@2722.5,3700
  BottomLayer w5: v2(1465,2335) 1615,2335 1680,2270 3130,2270 3160,2240 3285.86,2240 3475,2429.14 3475,3075 3450,3100 3400,3100 3350,3050 3300,3050 3245,3105 3245,3205 2735.43,3714.57 v1@2675,3714.57 ; v1(2500,3714.57) 2500.43,3715 v1(2675,3715) v1@2674.57,3714.57
PA5: CN9.56 JP15.2 U6.6 U8.41 | length 5734
  TopLayer w5: U8.41@2454.13,3734.25 v1(2525.75,3734.25) ; U6.6@2900,4425 2900,4465 2930,4495 2990,4495 3015,4470 3015,4250.15 3065,4200.15 3065,3590 3025,3550 v1(3025,3450)
  BottomLayer w5: JP15.2@1450,2550 1400,2500 1400,2350 1435,2315 1610,2315 1665,2260 3115,2260 3145,2230 3290,2230 3485,2425 3485,3115 3450,3150 CN9.56@3425,3150 3375,3100 3300,3100 3255,3145 3255,3220 2740.75,3734.25 v1(2525.75,3734.25)
PA6: CN9.55 JP3.1 R46.1 U8.42 | length 3677.1
  TopLayer w5: U8.42@2454.13,3753.94 v1(2501.06,3753.94) ; R46.1@2927.5,3975 3045,3975 ; v1(2975,3525) 2975,3550 3045,3620 3045,4191.86 2975,4261.86 v1(2975,4450) ; 3045,3970 3040,3975 3045,3980
  BottomLayer w5: v1(2501.06,3753.94) 2746.06,3753.94 3265,3235 3265,3185 3300,3150 CN9.55@3325,3150 ; v1(2975,4450) 2955,4470 2955,4637.57 3030,4712.57 3030,5620 2975,5675 JP3.1@2975,5800
PA7: CN1.5 CN9.54 U6.5 U8.43 | length 4211.6
  TopLayer w5: U8.43@2454.13,3773.62 v1(2526.38,3773.62) ; U6.5@2950,4425 2950,4460 2965,4475 2990,4475 3005,4460 3005,4246 3055,4196 3055,3605 2999.58,3549.58 v1(2999.58,3525.42)
  BottomLayer w5: v1(2526.38,3773.62) 2751.38,3773.62 3275,3250 3275,3225 3300,3200 3375,3200 CN9.54@3425,3250 ; v1(2975,4475) 2975,4643.43 3040,4708.43 3040,6140 3075,6175 3075,6250 CN1.5@3025,6300
PA8: CN1.3 CN8.6 TP6.1 U8.100 | length 5463.5
  TopLayer w5: v2(1025,5450) 1395,5820 1395,6270 1525,6400 3025,6400 CN1.3@3125,6300 ; U8.100@1837.99,4429.13 1837.99,4522.01 1805,4555 1805,4630 1865,4690 2315,4690 TP6.1@2375,4750
  BottomLayer w5: CN8.6@725,5650 825,5650 1200,5275 1200,4900 1495,4605 1770,4605 1837.99,4537.01 v1(1837.99,4500)
PA9: CN1.7 CN8.7 R50.2 U7.13 U8.101 | length 6163.9
  TopLayer w5: v2(1024.5,5425.5) 1405,5806 1405,6255 1540,6390 2835,6390 CN1.7@2925,6300 ; R50.2@1225,3594.5 v1(1225,3625) 1240.75,3640.75 U7.13@1240.75,3675.39 ; v1(1500,3575) 1514.14,3575 1564.14,3625 1640,3625 1805,3790 1805,3816.72 2015.11,4026.82 2015.11,4159.89 1818.31,4356.69 v1(1818.31,4475)
  BottomLayer w5: CN8.7@625,5550 675,5600 850,5600 1190,5260 1190,4885 1480,4595 1755,4595 1818.31,4531.69 v1(1818.31,4475) ; v1(1225,3625) 1275,3575 v1(1500,3575)
PA10: CN8.8 JP5.2 U8.102 | length 1814.5
  TopLayer w5: U8.102@1798.62,4429.13 v1(1798.62,4500)
  BottomLayer w5: CN8.8@725,5550 875,5550 975,5450 975,5300 1180,5095 1180,4870 1465,4585 1740,4585 1798.62,4526.38 v1(1798.62,4500)
PA11: CN8.12 R100.1 U8.103 U16.5 | length 9373.1
  TopLayer w5: U8.103@1778.94,4429.13 v1(1778.94,4475) ; R100.1@3969.5,900 3969.5,929.5 3990,950 4014.61,974.61 U16.5@4075,974.61
  BottomLayer w5: v1(1778.94,4475) 1778.94,4521.06 1725,4575 1450,4575 1170,4855 1170,4905 CN8.12@725,5350 700,5350 650,5300 600,5300 450,5150 450,2305 600,2155 1420,2155 1455,2120 1880,2120 1915.89,2084.11 1984.11,2084.11 2050,2150 2507.57,2150 2720,1937.57 2720,1410 2910,1220 3062.57,1220 3157.57,1125 3460,1125 3500,1165 3760,1165 3975,950 v2(3975,935)
PA12: CN8.13 R99.1 U8.104 | length 8639.8
  TopLayer w5: U8.104@1759.25,4429.13 v1(1759.25,4500) ; R99.1@3200,902.5 3227.5,902.5 3325,1000 v2(3325,1150)
  BottomLayer w5: v1(1759.25,4500) 1759.25,4515.75 1710,4565 1435,4565 1160,4840 1160,4890 750,5300 675,5300 CN8.13@625,5250 600,5250 460,5110 460,2315 610,2165 1435,2165 1470,2130 1895,2130 1930.89,2094.11 1969.11,2094.11 2035,2160 2511.72,2160 2730,1941.72 2730,1415 2915,1230 3066.72,1230 3131.72,1165 3310,1165 v2(3325,1150)
PA13: CN8.14 D4.3 RS1.3 U8.105 U14.25 U14.27 | length 7741.3
  TopLayer w5: U8.105@1739.57,4429.13 v1(1739.57,4475) ; v2(1950,2110) 2010,2110 2025,2125 2350,2125 2400,2075 2400,1775 2435,1740 D4.3@2475.5,1740 2475.5,1625 2525,1575.5 2525,1410 2541.1,1393.9 U14.27@2582.68,1393.9 ; 2400,2045 2405,2050 2400,2055 ; 2400,2050 2685,2050 2700.79,2065.79 RS1.3@2700.79,2077 ; 2525,1426.54 2531.73,1433.27 2525,1440 ; 2525,1433.27 U14.25@2582.68,1433.27
  BottomLayer w5: CN8.14@700,5250 650,5200 600,5200 470,5070 470,2325 620,2175 1450,2175 1485,2140 1910,2140 1940,2110 v2(1950,2110) ; CN8.14@725,5250 775,5250 1150,4875 1150,4825 1420,4555 1695,4555 1739.57,4510.43 v1(1739.57,4475)
PA14: CN8.15 D7.3 RS1.5 U8.109 U14.15 U14.26 | length 7691.3
  TopLayer w5: v1(1525,4350) 1530.51,4344.49 U8.109@1595.87,4344.49 ; v2(1975,2130) 2005,2130 2015,2140 2360,2140 v2(2425,2075) ; v2(2475,2000) 2475,1825 2550,1750 2550,1550 2625,1475 2625,1450 2625,1413.58 ; v2@2475.5,2000.5 2500,2025 2700,2025 2720.47,2045.47 RS1.5@2720.47,2077 ; U14.26@2582.68,1413.58 2763.58,1413.58 2818.9,1468.9 U14.15@2818.9,1492.32 ; 2620,1413.58 2625,1418.58 2630,1413.58
  BottomLayer w5: v1(1525,4350) 1320,4555 1320,4630 1140,4810 1140,4835 775,5200 675,5200 CN8.15@625,5150 600,5150 480,5030 480,2335 630,2185 1465,2185 1500,2150 1930,2150 1950,2130 v2(1975,2130) ; v2(2425,2075) 2475,2025 v2(2475,2000)
PA15: CN8.16 D8.3 RS1.9 U8.110 U14.17 | length 7332.3
  TopLayer w5: v1(1550,4325) 1550.2,4324.8 U8.110@1595.87,4324.8 ; v2(2000,2150) 2400,2150 2450,2100 2750,2100 2759.84,2090.16 v2(2759.84,2050) ; U14.17@2779.53,1492.32 2779.53,1519.53 2825,1565 D8.3@2825,1750
  BottomLayer w5: v1(1550,4325) 1525,4325 1310,4540 1310,4615 1130,4795 1130,4820 800,5150 700,5150 650,5100 600,5100 490,4990 490,2345 640,2195 1480,2195 1515,2160 1940,2160 1950,2150 v2(2000,2150) ; v2(2759.84,2050) 2759.84,2015.16 2850,1925 2850,1700 v2(2825,1675)
PB0: CN1.9 CN9.51 U8.46 | length 4088.2
  TopLayer w5: U8.46@2454.13,3832.68 v1(2502.32,3832.68) ; v1(3050,4375) 3070,4355 3070,4237.57 3095,4212.57 3095,3545.33 v1(3074.83,3525.17)
  BottomLayer w5: v1(2502.32,3832.68) 2767.32,3832.68 3250,3350 CN9.51@3325,3350 ; CN1.9@2825,6300 2775,6250 2775,5850 3020,5605 3020,4716.72 2940,4636.72 2940,4460 3025,4375 v1(3050,4375)
PB1: CN1.13 CN9.47 U8.47 | length 4021.7
  TopLayer w5: U8.47@2454.13,3852.36 v1(2527.64,3852.36) ; v1(3050,4350) 3060,4340 3060,4233.43 3085,4208.43 3085,3560 v2(3075,3550)
  BottomLayer w5: v1(2527.64,3852.36) 2772.64,3852.36 v2(3075,3550) CN9.47@3325,3550 ; CN1.13@2625,6300 2675,6250 2675,5925 3010,5590 3010,4720.86 2930,4640.86 2930,4445 3025,4350 v1(3050,4350)
PB2: CN9.45 R53.1 U8.48 | length 1141.6
  TopLayer w5: U8.48@2454.13,3872.05 v1(2502.95,3872.05) ; R53.1@2955.5,3500 2955.5,3555.5 3025,3625 v2(3025,3650)
  BottomLayer w5: v1(2502.95,3872.05) 2550,3872.05 2559.68,3862.36 2782.64,3862.36 2970,3675 3000,3675 v2(3025,3650) CN9.45@3325,3650
PB3: CN8.40 D5.3 RS1.7 U8.133 U14.16 U14.31 | length 6134.8
  TopLayer w5: v1(1527.05,3872.05) U8.133@1595.87,3872.05 ; U14.31@2582.68,1315.16 2716.02,1315.16 2900,1499.14 2900,1775 2825.5,1849.5 D5.3@2825.5,1940 ; v2(2725,2000) 2740.16,2015.16 RS1.7@2740.16,2077 ; U14.16@2799.21,1492.32 2799.21,1524.21 2825,1550 2900,1550 ; 2900,1545 2895,1550 2900,1555
  BottomLayer w5: v1(1527.05,3872.05) 1502.95,3872.05 1425,3950 700,3950 650,3900 600,3900 560,3860 560,2415 710,2265 1585,2265 1660,2190 2535,2190 v2(2825,1900)
PB4: C57.2 CN8.41 D9.3 JP12.2 RS1.11 U8.134 U14.19 | length 6270.7
  TopLayer w5: v1(1546.73,3852.36) U8.134@1595.87,3852.36 ; U14.19@2740.16,1492.32 2740.16,1515.16 2775,1550 2775,1595 2740,1630 2740,1685 2685,1740 2610,1740 2575,1775 2575,1925 2625,1975 2725,1975 2779.53,2029.53 2779.53,2094.53 2785,2100 2835,2100 2850,2115 2850,2150 2952.5,2252.5 C57.2@3025,2252.5 JP12.2@3025,2475
  BottomLayer w5: v1(1546.73,3852.36) 1497.64,3852.36 1450,3900 675,3900 CN8.41@625,3850 600,3850 570,3820 570,2425 720,2275 1600,2275 1675,2200 2550,2200 2749.55,2000.45 v2(2750.45,2000.45)
PB5: C6.2 CN1.29 CN8.42 U8.135 | length 4146.1
  TopLayer w5: v2(1400,4850) 1400,3925 1492.32,3832.68 U8.135@1595.87,3832.68 ; CN1.29@1825,6300 1875,6250 1875,6100 1975,6000 C6.2@1975,5852.5
  BottomLayer w5: CN8.42@725,3850 775,3850 800,3875 1450,3875 1492.32,3832.68 v1(1527.68,3832.68) ; v2(1400,4850) 1375,4875 1375,5475 1775,5875 1775,6250 CN1.29@1825,6300
PB6: CN8.43 R38.2 U8.136 | length 2940.9
  TopLayer w5: v1(1547.99,3812.99) 1687.99,3812.99 1920,4045 v1(1920,4120) ; v2(2135,4725) 2150,4740 2265,4740 2325,4800 2525,4800 2545,4780 2680,4780 2747.5,4847.5 R38.2@2770,4847.5
  BottomLayer w5: CN8.43@625,3750 675,3800 750,3800 800,3850 1450,3850 1487.01,3812.99 v1(1547.99,3812.99) ; v1(1920,4120) 1945,4145 1945,4311.15 2080,4446.15 2080,4515.86 2161.17,4597.02 2161.17,4638.83 2135,4665 v2(2135,4725)
PB7: CN8.44 JP6.2 U8.137 | length 2746.7
  TopLayer w5: v1(1528.31,3793.31) 1683.31,3793.31 1935,4045 1935,4115 1940,4120 1940,4160 v1(1925,4175) ; v2(2125,4775) 2150,4800 2255,4800 2285,4830 2480,4830 2575,4925 JP6.2@2600,4925
  BottomLayer w5: CN8.44@725,3750 750,3750 825,3825 1450,3825 1481.69,3793.31 v1(1528.31,3793.31) ; v1(1925,4175) 1925,4305.29 2070,4450.29 2070,4520 2151.17,4601.17 2151.17,4632.98 2115,4669.14 2115,4765 v2(2125,4775)
PB8: CN8.45 R37.2 U8.139 | length 2979.6
  TopLayer w5: v1(1551.06,3753.94) 1698.94,3753.94 1975,4030 1975,4055 v1(1955,4075) ; v2(2155,4775) 2250,4775 2295,4820 2495,4820 2540,4865 2635,4865 2652.5,4847.5 R37.2@2695,4847.5
  BottomLayer w5: CN8.45@625,3650 675,3700 750,3700 850,3800 1450,3800 1496.06,3753.94 v1(1551.06,3753.94) ; v1(1955,4075) 1955,4307.01 2090,4442.01 2090,4511.72 2171.17,4592.88 2171.17,4648.83 2155,4665 v2(2155,4775)
PB9: CN8.46 R35.2 U8.140 | length 3052.6
  TopLayer w5: v1(1525.75,3734.25) 1694.25,3734.25 1985,4025 1985,4090 v1(1975,4100) ; v2(2175,4715) 2265,4715 2340,4790 2510,4790 2530,4770 2695,4770 2740,4815 2865,4815 2897.5,4847.5 R35.2@2925,4847.5
  BottomLayer w5: CN8.46@725,3650 745,3650 870,3775 1450,3775 1490.75,3734.25 v1(1525.75,3734.25) ; v1(1975,4100) 1975,4200 2100,4325 2100,4505 2181.17,4586.17 2181.17,4663.83 2175,4670 v2(2175,4715)
PB10: CN9.24 R77.2 U8.69 | length 3263.6
  TopLayer w5: R77.2@2372.5,2525 2372.5,2552.5 2400,2580 2400,2625 2635,2860 2635,3860 2725,3950 v1(2725,4175) ; U8.69@2454.13,4285.43 2560.43,4285.43 2585,4310 2585,4410 2752.07,4577.07 3152.07,4577.07 3275,4700 3375,4700 CN9.24@3425,4750
  BottomLayer w5: v1(2525,4285.43) 2614.57,4285.43 v1(2725,4175)
PB11: CN9.23 R72.2 U8.70 | length 3066.5
  TopLayer w5: R72.2@2372.5,2600 2372.5,2622.5 2625,2875 2625,3864.14 2705,3944.14 v1(2705,4220) ; U8.70@2454.25,4305 v1(2545,4305) ; v1@2545,4305.12 2555.12,4305.12 2575,4325 2575,4425 2737.07,4587.07 3137.07,4587.07 3300,4750 CN9.23@3325,4750
  BottomLayer w5: v1(2545,4305) 2620,4305 v1(2705,4220)
PB12: CN1.21 CN9.22 JP11.1 U8.73 | length 5761.3
  TopLayer w5: v2(1960,3760) 1960,3790.86 2400,4230.86 2400,4294.49 2369.49,4325 2369.49,4469.49 2400,4500 2625,4500 2722.07,4597.07 2947.07,4597.07 2980,4630 3155,4630 3275,4750 3275,4775 3300,4800 3375,4800 CN9.22@3425,4850
  BottomLayer w5: v2(1960,3760) 1960,3565 2065,3460 2065,2910 JP11.1@2150,2825 ; CN1.21@2225,6300 2275,6350 3050,6350 3085,6315 3085,6160 3050,6125 3050,4700 3000,4650 v1(3000,4630)
PB13: CN6.5 CN9.21 U8.74 | length 6764.7
  TopLayer w5: CN6.5@368.35,5193.7 493.7,5193.7 565,5265 565,5915 v2(690,6040) ; U8.74@2349.8,4429.13 2349.8,4474.8 2385,4510 2610,4510 2707.07,4607.07 2932.07,4607.07 2975,4650 3150,4650 3265,4765 3265,4815 3300,4850 CN9.21@3325,4850
  BottomLayer w5: v2(690,6040) 965,6040 1345,6420 3255,6420 3495,6180 3495,4945 3450,4900 3375,4900 CN9.21@3325,4850
PB14: CN9.20 R24.2 U8.75 | length 6704.9
  TopLayer w5: R24.2@502.5,5100 550,5100 575,5125 575,5900 v2(674.94,5999.94) ; U8.75@2330.12,4429.13 2330.12,4480.12 2370,4520 2595,4520 2692.07,4617.07 2917.07,4617.07 2960,4660 3135,4660 3255,4780 3255,4855 3300,4900 3375,4900 CN9.20@3425,4950
  BottomLayer w5: v2(674.94,5999.94) 705,6030 980,6030 1360,6410 3240,6410 3485,6165 3485,5010 CN9.20@3425,4950
PB15: CN6.3 CN9.18 U8.76 | length 6644.4
  TopLayer w5: CN6.3@368.35,5280.31 409.69,5280.31 420,5270 465,5270 475,5280 475,5400 545,5470 545,5945 690,6090 1065,6090 v2(1075,6100) ; U8.76@2310.43,4429.13 2310.43,4485.43 2355,4530 2580,4530 2677.07,4627.07 2902.07,4627.07 2945,4670 3120,4670 3245,4795 3245,4945 3300,5000 3375,5000 CN9.18@3425,5050
  BottomLayer w5: v2(1075,6100) 1375,6400 3225,6400 3475,6150 3475,5100 CN9.18@3425,5050
PC0: C12.2 CN9.66 R7.2 R9.2 U8.26 | length 5106.7
  TopLayer w5: v1(2172.64,3502.36) U8.26@2172.64,3570.87 ; R7.2@2575,5797.5 2575,5694.5 C12.2@2675,5694.5 ; v1(2600.12,3049.88) 2615,3064.76 2615,3870 2685,3940 2685,4260 v1(2775,4350)
  BottomLayer w5: v1(2172.64,3502.36) 2172.64,3477.36 2875,2775 3125,2775 3295,2605 3380,2605 CN9.66@3425,2650 ; v1(2575,5725) 2600,5700 2875,5700 3000,5575 3000,4725 2780.59,4505.59 2780.59,4355.59 v1(2775,4350)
